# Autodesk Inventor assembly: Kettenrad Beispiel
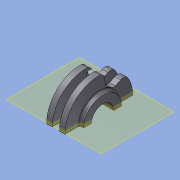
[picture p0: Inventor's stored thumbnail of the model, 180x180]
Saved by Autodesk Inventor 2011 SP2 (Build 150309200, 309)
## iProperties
Created: 2013-10
Part Number: Kettenrad Beispiel
Document SubType Name: Schweißkonstruktion
Mass: 161718 g
Surface Area: 8496.04 cm^2
Volume: 20627.3 cm^3
Density: 7.84 g/cm^3
Weld Material: Geschweißter Stahl (weich)
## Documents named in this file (2)
- C:\VaultWS\Designs\MinPro\Arbeitsordner\3_Pers_Arbeitso\Schmid\Kettenrad 55227341100000 Beispiel\Kettenrad Beispiel.iam
- C:\VaultWS\Designs\MinPro\Arbeitsordner\3_Pers_Arbeitso\Schmid\Kettenrad 55227341100000 Beispiel\2.iam
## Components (1 placed, 1 different names)
1. 2:1 [sub-assembly] — Tangential:1
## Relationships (1: Tangent 1)
- Tangential:1: 2:1
## Named parameters: Maß_M1Y = 174 mm
